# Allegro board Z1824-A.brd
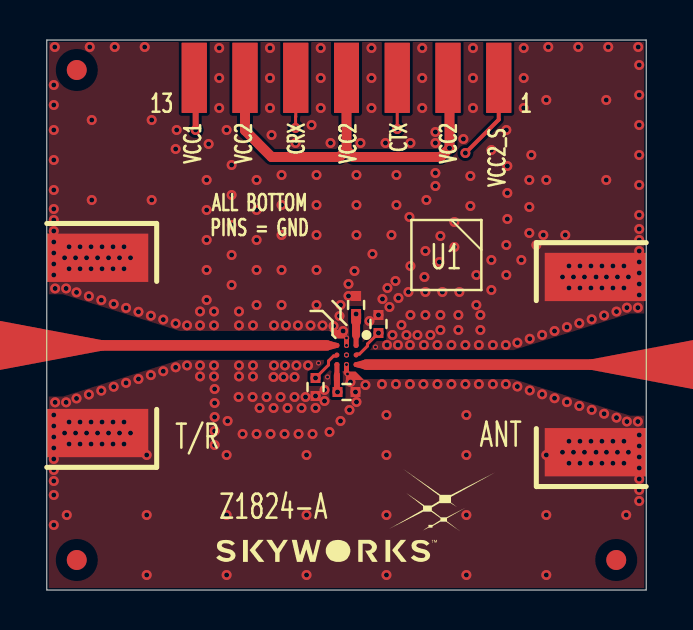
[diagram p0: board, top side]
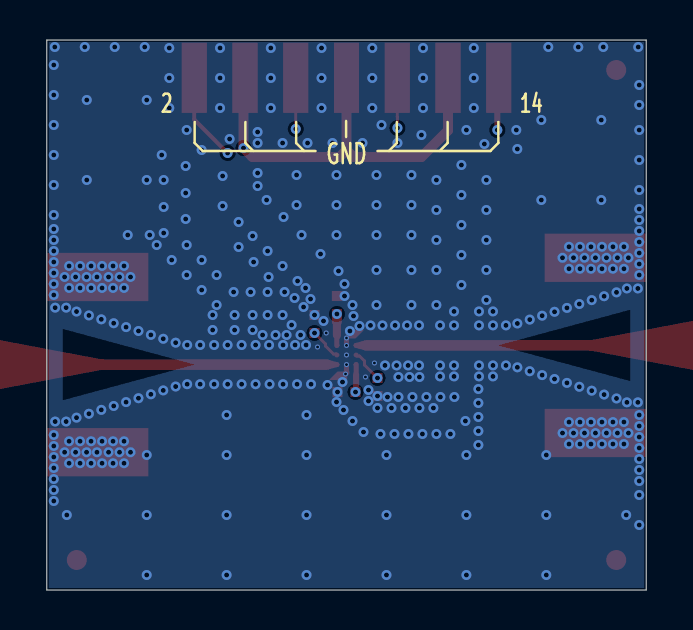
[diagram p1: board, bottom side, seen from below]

Outline 30 x 27.5 mm; copper layers: TOP, L2, L3, BOTTOM. Coordinates in mm from the lower left corner of the outline.
Outline path: 0,27.5 0,0 30,0 30,27.5 0,27.5

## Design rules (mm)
constraint set DEFAULT: min track width 0.15
net group SE50: nets ANT T_R
nets with their own width: nets VCC1
nets with their own width: min track width 0.5; nets VCC2

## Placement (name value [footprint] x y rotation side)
C3  1uF  [SMDC1000X500]  15 9.9 0 top
C4  DNI  [SMDC1000X500]  13.45 10.15 270 top
C5  DNI  [SMDC1000X500]  16.6 13.3 90 top
C7  1uF  [SMDC1000X500]  15.48 14.25 90 top
C8  10pF  [SMDC600X300]  14.82 10.62 0 top
C9  DNI  [SMDC600X300]  15.18 12.9 180 top
J1  SMA  [SMA_END_E]  0 12.23 90 top
J2  SMA  [SMA_END_E]  30 11.27 270 top
J3  HEADER 7X2 STRADDLE-MOUNT  [TSW-107-07-G-D_EDGE]  15 27.5 0 top
NOREF  -  []  0 0 90 top
NOREF#2  -  [unnamed#2]  1.5 26 0 top
NOREF#3  -  []  -0.48 74.53 0 top
NOREF#4  -  [unnamed#2]  1.5 1.5 0 top
NOREF#5  -  [unnamed#2]  28.5 1.5 0 top
NOREF#6  -  []  8.05 0.93 0 top
NOREF#7  -  []  0 27.5 0 top
NOREF#8  -  []  -110 -58.47 0 top
U1  SKY66415-11  [MK3187A41_A]  15 11.75 270 top

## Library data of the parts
C3-C5 C7-C9 = C
J1 J2 = RF_3pin
J3 = HEADER 7X2
U1 = SKY66415-11

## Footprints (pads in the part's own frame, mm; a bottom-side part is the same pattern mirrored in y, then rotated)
MK3187A41_A
  round 0.25 smd: A1(-0.48,0.48) A2(0,0.48) A3(0.48,0.48) B1(-0.48,0) B2(0,0) B3(0.48,0) C1(-0.48,-0.48) C2(0,-0.48) C3(0.48,-0.48)
SMA_END_E
  custom 0.684x0.684 smd: 1(0,0)
  rect 2.413x5.08 smd: 2(4.381,-2.54) 3(-4.381,-2.54)
SMDC600X300
  rect 0.3x0.3 smd: 1(-0.3,0) 2(0.3,0)
SMDC1000X500
  rect 0.5x0.5 smd: 1(-0.45,0) 2(0.45,0)
TSW-107-07-G-D_EDGE
  rect 1.25x3.5 smd: 1(7.62,-1.89) 2(7.62,-1.89) 3(5.08,-1.89) 4(5.08,-1.89) 5(2.54,-1.89) 6(2.54,-1.89) 7(0,-1.89) 8(0,-1.89) 9(-2.54,-1.89) 10(-2.54,-1.89) 11(-5.08,-1.89) 12(-5.08,-1.89) 13(-7.62,-1.89) 14(-7.62,-1.89)
unnamed#2
  round 1 smd: (0,0)

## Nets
GND: C3.2 C4.2 C5.2 C7.2 C8.2 C9.2 J1.2 J1.3 J2.2 J2.3 J3.2 J3.4 J3.6 J3.8 J3.10 J3.12 J3.14 U1.B1 U1.B2 U1.B3
VCC1: C3.1 C8.1 J3.13 U1.C3
VCC2: C7.1 C9.1 J3.1 J3.3 J3.7 J3.11 U1.A1(VCC2)
ANT: J2.1(SIG) U1.A3
CRX: C4.1 J3.9 U1.C2
CTX: C5.1 J3.5 U1.A2
T_R: J1.1(SIG) U1.C1

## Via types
v1: diameter 0.5, hole 0.25, TOP to BOTTOM, 420 vias
v2: diameter 0.25, hole 0.15, TOP to BOTTOM, 9 vias

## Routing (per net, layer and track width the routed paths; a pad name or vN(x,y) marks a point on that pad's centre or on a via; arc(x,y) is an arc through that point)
GND: length 0.9
  TOP w0.25: v2(15,12.6) v2(15,12.23) ; v2(15,11.27) 15,10.85 v2(15.05,10.8)
  vias: v1(0.35,25.25) v1(0.35,24.25) v1(0.35,23) v1(0.35,21.5) v1(0.35,20) v1(0.35,19.05) v1(0.35,18.5) v1(0.35,17.95) v1(0.35,17.4) v1(0.35,16.85) v1(0.35,16.3) v1(0.35,15.75) v1(0.35,8.75) v1(0.35,8.2) v1(0.35,7.65) v1(0.35,7.1) v1(0.35,6.55) v1(0.35,6) v1(0.35,5.45) v1(0.35,4.75) v1(0.35,3.25) v1(0.4,27.15) v1(0.42,15.08) v1(0.42,9.38) v1(0.89,16.61) v1(0.89,7.85) v1(0.97,15.08) v1(0.97,9.38) v1(1,3.75) v1(1.12,17.16) v1(1.12,16.06) v1(1.12,8.4) v1(1.12,7.3) v1(1.44,16.61) v1(1.44,7.85) v1(1.49,14.88) v1(1.49,9.58) v1(1.66,17.16) v1(1.66,16.06) v1(1.66,8.4) v1(1.66,7.3) v1(1.99,16.61) v1(1.99,7.85) v1(2.11,14.69) v1(2.11,9.77) v1(2.15,27.15) v1(2.25,23.5) v1(2.25,19.5) v1(2.21,17.16) v1(2.21,16.06) v1(2.21,8.4) v1(2.21,7.3) v1(2.54,16.61) v1(2.54,7.85) v1(2.73,14.49) v1(2.73,9.97) v1(2.77,17.16) v1(2.77,16.06) v1(2.77,8.4) v1(2.77,7.3) v1(3.09,16.61) v1(3.09,7.85) v1(3.31,17.16) v1(3.31,16.06) v1(3.35,14.3) v1(3.35,10.16) v1(3.31,8.4) v1(3.31,7.3) v1(3.4,27.15) v1(3.64,16.61) v1(3.64,7.85) v1(3.87,17.16) v1(3.87,16.06) v1(3.87,8.4) v1(3.87,7.3) v1(3.97,14.1) v1(3.97,10.36) v1(4.19,16.61) v1(4.19,7.85) v1(4.59,13.91) v1(4.59,10.55) v1(4.9,27.15) v1(5,6.75) v1(5,3.75) v1(5,0.75) v1(5.25,23.5) v1(5.25,19.5) v1(5.21,13.72) v1(5.21,10.74) v1(5.83,13.52) v1(5.83,10.94) v1(6.45,22.05) v1(6.45,13.33) v1(6.45,11.13) v1(6.5,23) v1(7.02,13.23) v1(7.02,11.23) v1(7.67,13.93) v1(7.67,13.23) v1(7.67,11.23) v1(7.67,10.68) v1(8,20.5) v1(8,19) v1(8,17.5) v1(8,16) v1(8,14.5) v1(8.1,22.3) v1(8.37,13.93) v1(8.37,13.23) v1(8.37,11.23) v1(8.37,10.68) v1(8.4,10.05) v1(8.4,9.35) v1(8.4,8.65) v1(8.4,7.95) v1(8.4,7.25) v1(8.63,27.1) v1(8.63,25.6) v1(8.63,24.1) v1(9,23) v1(9.05,8.45) v1(9,6.75) v1(9,3.75) v1(9,0.75) v1(9.25,21.25) v1(9.25,19.75) v1(9.25,18.25) v1(9.25,16.75) v1(9.25,15.25) v1(9.62,13.93) v1(9.62,13.23) v1(9.62,11.23) v1(9.62,10.68) v1(9.6,9.65) v1(9.8,7.8) v1(10.32,13.23) v1(10.32,11.23) v1(10.32,10.68) v1(10.3,9.65) v1(10.5,20.5) v1(10.5,19) v1(10.5,17.5) v1(10.5,16) v1(10.5,14.25) v1(10.5,7.8) v1(10.65,9.1) v1(11,9.65) v1(11.17,27.1) v1(11.17,25.6) v1(11.17,24.1) v1(11.25,22.75) v1(11.2,7.8) v1(11.37,13.23) v1(11.37,11.23) v1(11.35,10.65) v1(11.35,9.1) v1(11.7,9.65) v1(11.75,20.75) v1(11.75,19.25) v1(11.75,17.75) v1(11.75,16) v1(11.75,14.25) v1(11.92,11.23) v1(11.85,10.65) v1(11.9,7.8) v1(11.97,13.23) v1(12.05,9.1) v1(12.4,10.65) v1(12.4,9.65) v1(12.45,22.35) v1(12.49,11.23) v1(12.57,13.23) v1(12.6,7.8) v1(12.75,9.1) v1(12.95,9.65) v1(13,6.75) v1(13,3.75) v1(13,0.75) v1(13.07,11.23) v1(13.25,23.25) v1(13.2,13.23) v1(13.3,7.8) v1(13.45,9.7) v1(13.45,9.1) v1(13.5,20.75) v1(13.5,19.25) v1(13.5,17.75) v1(13.5,16) v1(13.5,14.25) v1(13.71,27.1) v1(13.71,25.6) v1(13.71,24.1) v1(13.8,13.23) v1(13.9,10) v1(13.9,9.45) v1(14.2,22.35) v1(14.15,7.9) v1(14.35,13.2) v1(14.7,14.25) v1(14.65,13.7) v1(14.7,8.45) v1(14.83,12.95) v1(15.1,15.3) v1(15.1,14.7) v1(15.15,9) v1(15.2,10.4) v1(15.4,15.95) v1(15.5,20.75) v1(15.5,19.25) v1(15.5,17.75) v1(15.45,9.9) v1(15.5,9.4) v1(15.7,22.35) v1(15.95,10.25) v1(16.15,13.45) v1(16.25,27.1) v1(16.25,25.6) v1(16.25,24.1) v1(16.3,16.8) v1(16.6,13.75) v1(16.8,14.55) v1(16.77,10.29) v1(16.95,22.35) v1(17.05,15.1) v1(17.02,12.25) v1(17,8.75) v1(17,6.75) v1(17,3.75) v1(17,0.75) v1(17.15,14.15) v1(17.25,17.75) v1(17.3,12.75) v1(17.5,20.75) v1(17.5,19.25) v1(17.45,15.45) v1(17.48,10.29) v1(17.6,14.6) v1(17.57,12.25) v1(17.75,13.25) v1(18,12.75) v1(18.15,18.65) v1(18.1,14.9) v1(18.2,22.35) v1(18.2,16.2) v1(18.2,13.75) v1(18.18,12.25) v1(18.18,10.29) v1(18.55,12.75) v1(18.79,27.1) v1(18.79,25.6) v1(18.79,24.1) v1(18.9,15.65) v1(18.88,12.25) v1(18.85,10.29) v1(19,19.5) v1(18.95,16.95) v1(18.95,14.9) v1(18.95,13.75) v1(19.2,12.75) v1(19.45,22.9) v1(19.45,22.35) v1(19.45,20.85) v1(19.45,20.2) v1(19.55,12.25) v1(19.55,10.29) v1(19.7,17.7) v1(19.65,16.4) v1(19.7,13.75) v1(19.7,13) v1(19.8,14.9) v1(20.25,12.25) v1(20.25,10.29) v1(20.4,18.4) v1(20.4,17.15) v1(20.6,13.75) v1(20.6,13) v1(20.65,14.9) v1(20.85,22.55) v1(20.95,12.25) v1(20.95,10.29) v1(21,8.75) v1(21,6.75) v1(21,3.75) v1(21,0.75) v1(21.2,20.7) v1(21.2,19.2) v1(21.33,27.1) v1(21.33,25.6) v1(21.33,24.1) v1(21.5,15.75) v1(21.5,14.25) v1(21.62,12.25) v1(21.62,10.29) v1(21.7,13.75) v1(21.7,13) v1(22.25,22) v1(22.25,16.5) v1(22.25,15) v1(22.32,12.25) v1(22.32,10.29) v1(23,23) v1(23,17.25) v1(23,15.75) v1(22.98,12.25) v1(22.98,10.29) v1(23.05,21.2) v1(23.05,19.85) v1(23.05,18.55) v1(23.55,12.37) v1(23.55,10.17) v1(23.75,16.5) v1(23.87,27.1) v1(23.87,25.6) v1(23.87,24.1) v1(24.25,21.75) v1(24.15,20.5) v1(24.15,19.15) v1(24.15,17.85) v1(24.17,12.56) v1(24.17,9.98) v1(24.5,17.25) v1(24.85,17.75) v1(24.79,12.76) v1(24.79,9.78) v1(25,24.5) v1(25,20.5) v1(25,6.75) v1(25,3.75) v1(25,0.75) v1(25.1,27.15) v1(25.41,12.95) v1(25.41,9.59) v1(25.81,15.65) v1(25.81,6.89) v1(25.95,17.75) v1(26.03,13.14) v1(26.03,9.4) v1(26.13,16.2) v1(26.13,15.1) v1(26.13,7.44) v1(26.13,6.34) v1(26.36,15.65) v1(26.36,6.89) v1(26.6,27.15) v1(26.69,16.2) v1(26.69,15.1) v1(26.65,13.34) v1(26.65,9.2) v1(26.69,7.44) v1(26.69,6.34) v1(26.91,15.65) v1(26.91,6.89) v1(27.23,16.2) v1(27.23,15.1) v1(27.23,7.44) v1(27.23,6.34) v1(27.27,13.53) v1(27.27,9.01) v1(27.49,15.65) v1(27.49,6.89) v1(27.79,16.2) v1(27.79,15.1) v1(27.79,7.44) v1(27.79,6.34) v1(27.89,13.73) v1(27.89,8.81) v1(28,24.5) v1(28,20.5) v1(28.01,15.65) v1(28.01,6.89) v1(28.1,27.15) v1(28.34,16.2) v1(28.34,15.1) v1(28.34,7.44) v1(28.34,6.34) v1(28.51,13.92) v1(28.51,8.62) v1(28.56,15.65) v1(28.56,6.89) v1(28.88,16.2) v1(28.88,15.1) v1(28.88,7.44) v1(28.88,6.34) v1(29.03,14.12) v1(29.03,8.42) v1(29,3.75) v1(29.11,15.65) v1(29.11,6.89) v1(29.6,27.15) v1(29.58,14.12) v1(29.58,8.42) v1(29.65,26.25) v1(29.65,24.75) v1(29.65,23.25) v1(29.65,21.75) v1(29.65,20.25) v1(29.65,18.75) v1(29.65,18.05) v1(29.65,17.5) v1(29.65,16.95) v1(29.65,16.4) v1(29.65,15.85) v1(29.65,15.3) v1(29.65,14.75) v1(29.65,7.75) v1(29.65,7.2) v1(29.65,6.65) v1(29.65,6.1) v1(29.65,5.55) v1(29.65,5) v1(29.65,4.45) v2(13.6,11.35) v2(14.05,10.65) v2(15,11.75) v2(16.02,12.85) v2(16.45,12.15)
VCC1: length 25.2
  TOP w0.25: 14.52,10.77 U1.C3
  TOP w0.3: 14.52,10.77 C8.1 14.52,9.93 v1(14.55,9.9) ; v1(7.45,23) 7.45,25.54 J3.13
  L3 w0.3: v1(7.45,23) 7.45,21.95 8.65,20.75 8.65,14.75 8.99,14.4 8.99,9.41 9.95,8.45 13.75,8.45 14.55,9.25 v1(14.55,9.9)
VCC2: length 47.4
  TOP w0.2: v1(20.95,21.85) 22.62,23.52 J3.1
  TOP w0.25: U1.A1 15.48,12.73
  TOP w0.4: 15.48,13.42 C9.1 15.48,12.73
  TOP w0.5: 15,22 15.35,21.65 19.71,21.65 v1(20.16,22.09) 20.16,24.89 20.08,24.97 J3.3 ; 15,22 J3.7 ; 15,22 14.65,21.65 11.25,21.65 9.92,22.98 J3.11 ; v1(15.48,13.8) 15.48,13.42
  L3 w0.15: 15.79,14.11 16.19,14.11 16.3,14.22 16.3,15.04 20.63,19.37 20.63,21.53 v1(20.95,21.85)
  L3 w0.5: v1(15.48,13.8) 15.79,14.11 15.79,15.24 20.16,19.61 v1(20.16,22.09)
ANT: length 14.5
  TOP w0.25: 16,11.27 U1.A3
  TOP w0.533: J2.1 16,11.27
CRX: length 20.4
  TOP w0.15: v1(13.45,10.6) 14.1,11.25 14.1,11.45 14.35,11.7 14.47,11.7 U1.C2 ; J3.9 12.46,23.66 12.45,23.65 v1(12.45,23.1)
  L3 w0.15: v1(13.45,10.6) 13,10.15 11.15,10.15 10.82,10.48 10.82,13.82 11.12,14.12 11.12,21.77 v1(12.45,23.1)
CTX: length 24.4
  TOP w0.15: U1.A2 15.53,11.8 15.65,11.8 16.05,12.2 16.05,12.3 v1(16.6,12.85) ; v1(17.54,23.05) J3.5
  L3 w0.15: v1(16.6,12.85) 18,14.25 20.8,14.25 23.6,17.05 23.6,21.55 21.7,23.45 17.94,23.45 v1(17.54,23.05)
T_R: length 14.5
  TOP w0.25: 14,12.23 U1.C1
  TOP w0.533: J1.1 14,12.23

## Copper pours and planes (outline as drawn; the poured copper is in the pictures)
GND on TOP, BOTTOM, L2, L3: 0.1,27.4 29.9,27.4 29.9,0.1 0.1,0.1

Small or netless copper shapes (teardrops, artwork), in the pictures only: 4 on TOP

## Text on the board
Ref Des/Silkscreen Bottom: GND
User.Comments: OVERALL BOARD THICKNESS (METAL-TO-METAL) = 1.5 mm +/- 10%
Ref Des/Silkscreen Top: ALL BOTTOM | PINS = GND | VCC1 | VCC2 | CRX | CTX | VCC2_S | T/R | Z1824-A | U1 | ANT
User.10: 2024-11-26
User.12: 2024-11-26
User.13: 14. | 2. | 7. | 1.  FABRICATE IN ACCORDANCE WITH IPC-6012, CLASS 2, ACCEPT PER IPC-A-600 CLASS 2 | 2.  MATERIAL: SEE DETAIL A FOR MATERIAL AND FINISHED THICKNESS. BEGINNING FOIL | THICKNESS 1/2-OZ MIN. BUT SHALL MEET THE MINIMUM REQUIREMENTS STATED IN DETAIL 'A'. | 3.  COPPER PLATE 0.025/0.038MM THICK IN THRU HOLE VIAS (APPROX. 0.038MM ON SURFACE). | 4.  FINISH: ENIG PER IPC-4552 | 5.  APPLY GREEN LIQUID PHOTOIMAGABLE SOLDERMASK OVER BARE COPPER (SMOBC) TO THE TOP | AND BOTTOM SURFACES OF THE PRINTED WIRING BOARD. | 6.  APPLY DESIGNATIONS TO TOP AND BOTTOM SURFACES USING PERMANENT SOLVENT INK AS DEFINED | BY THE ARTWORK. COLOR SHALL BE WHITE. | 7.  CONDUCTORS SPECIFIED IN DETAIL 'A' ARE CONTROLLED IMPEDANCE LINES AND SHALL BE TESTED FOR | FOR THE SPECIFIED IMPEDANCE(S). CONDUCTORS AND GAP MAY BE ADJUSTED TO ACHIEVE SPECIFIED IMPEDANCE. | VENDOR MUST INFORM SKYWORKS OF FINAL DIMENSIONS. | 8.  MINIMUM CONDUCTOR WIDTH IS 0.15MM. | 9.  MINIMUM CONDUCTOR TO CONDUCTOR SPACING IS 0.15MM. | 10. FINISHED BOARD THICKNESS SHALL BE PER DETAIL 'A'. | 11. LAYER TO LAYER REGISTRATION TO BE +/- 0.075MM. | 12. ALL HOLES SHALL BE LOCATED WITHIN HOLE TO PAD TANGENCY. | 13. SUPPLIER ID/PART NUMBER AND LOT NUMBER ARE REQUIRED TO BE LOCATED ON BOTTOM SURFACE. | 14. NOTED VIA DRILL HOLES SHALL BE FILLED WITH NON-CONDUCTIVE MATERIAL. | AND PLATED OVER WITH A MINIMUM OF 0.015MM OF CU. | 15. DRILLS =< 300um MAY HAVE TOLERANCE +75um/-FHS, BUT DO NOT COMBINE DRILLS.
User.33: SYMBOL | SIZE | 150.0 | 250.0 | PLATED | DRILL CHART: TOP to BOTTOM | ALL UNITS ARE IN MICRONS | QTY | 9 | 420 | 429 | TOLERANCE | +75.0/-75.0 | SEE NOTE | TOTAL HOLES:
